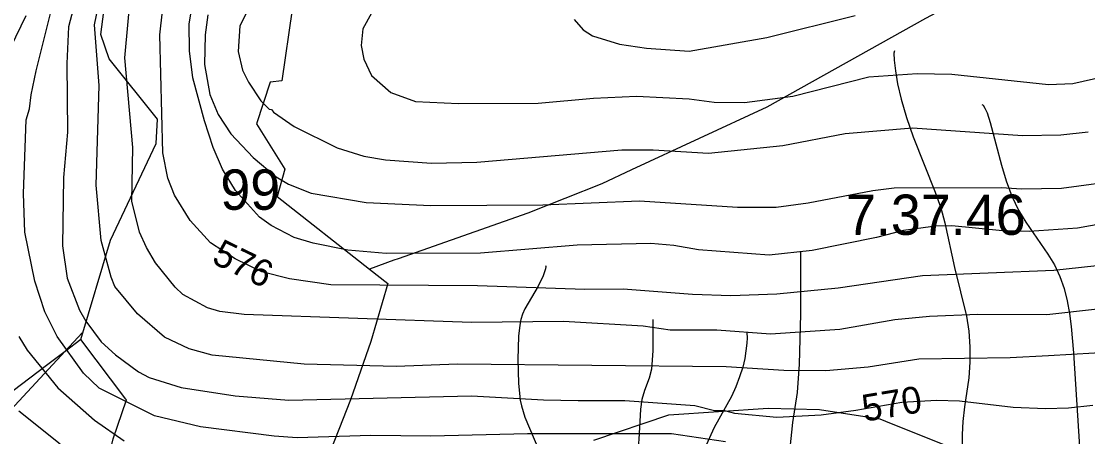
# Model space of a CAD drawing. Extents: x -709584 to -702006, y -1161789 to -1157496.
# Drawn here: x -707197.2 to -706800.1, y -1158463.2 to -1158308.6 of the extents above; entities that cross this region are included whole.
import ezdxf

# ---------------------------------------------------------------- set-up
doc = ezdxf.new("R2010")
doc.units = 0
for name, color, linetype in [('120_vrstevnice hlavní', 7, 'Continuous'), ('121_vrstevnice hlavní_popis', 7, 'Continuous'), ('122_vrstevnice základní', 7, 'Continuous'), ('408_BPEJ_linie', 7, 'Continuous'), ('409_BPEJ_popis', 7, 'Continuous'), ('411_akumulovaný odtok', 7, 'Continuous')]:
    doc.layers.add(name, color=color, linetype=linetype)

msp = doc.modelspace()

# ---------------------------------------------------------------- linework, layer by layer
at = {"layer": '120_vrstevnice hlavní'}
for points in [[(-707177.9, -1158304.1), (-707179.63, -1158310.68)], [(-707127.71, -1158306.12), (-707128.71, -1158313.55), (-707129, -1158324.7), (-707127, -1158335.84), (-707123.85, -1158343.27), (-707119.14, -1158350.41), (-707110.85, -1158359.27), (-707102.28, -1158366.41), (-707097.71, -1158369.13), (-707089.28, -1158372.56), (-707068.71, -1158375.99), (-707044.71, -1158377.13), (-707002.99, -1158376.84), (-706966.99, -1158375.41), (-706930.42, -1158377.7), (-706916.13, -1158377.7), (-706904.13, -1158376.13), (-706880.13, -1158371.56), (-706872.13, -1158370.56), (-706832.13, -1158370.41), (-706824.7, -1158370.98), (-706809.84, -1158370.7), (-706785.84, -1158367.41)], [(-707179.63, -1158310.68), (-707180.17, -1158324.22), (-707180, -1158349.84), (-707181.43, -1158366.7), (-707181.86, -1158392.13), (-707180.14, -1158404.13), (-707175.43, -1158416.13), (-707173.14, -1158420.13), (-707167.43, -1158427.84), (-707162.14, -1158432.7), (-707153.57, -1158438.99), (-707149.57, -1158441.13), (-707137.57, -1158444.84), (-707117.57, -1158447.99), (-707097.57, -1158449.56), (-707029.56, -1158447.99), (-707002.71, -1158449.42), (-706989.85, -1158449.7), (-706972.42, -1158449.7), (-706946.42, -1158451.56), (-706938.99, -1158453.42), (-706935.27, -1158453.42), (-706931.56, -1158454.42), (-706915.84, -1158455.85), (-706899.27, -1158454.99), (-706886.41, -1158453.27), (-706869.27, -1158450.27), (-706856.41, -1158449.56), (-706847.84, -1158449.84), (-706827.84, -1158452.13), (-706815.84, -1158452.7), (-706807.27, -1158452.42), (-706798.12, -1158451.42)]]:
    msp.add_lwpolyline(points, dxfattribs=at)
at = {"layer": '122_vrstevnice základní'}
for points in [[(-707194.14, -1158341.13), (-707193.54, -1158335.89), (-707191.58, -1158326.95), (-707186.28, -1158305.72), (-707183.48, -1158297.62), (-707179.57, -1158288.68), (-707172.29, -1158274.98), (-707165.57, -1158257.84), (-707139.57, -1158216.69), (-707132.14, -1158202.41), (-707128.71, -1158194.41), (-707111.71, -1158144.4), (-707107, -1158124.4), (-707102.85, -1158094.4), (-707101.71, -1158080.69), (-707101.85, -1158059.26), (-707103.28, -1158048.97), (-707105, -1158023.82), (-707101.71, -1157974.11)], [(-706792.12, -1158399.13), (-706812.7, -1158401.27), (-706861.56, -1158403.27), (-706892.99, -1158407.84), (-706915.84, -1158410.13), (-706932.99, -1158410.7), (-706947.27, -1158410.27), (-706972.99, -1158408.27), (-706987.28, -1158408.42), (-707027.28, -1158406.99), (-707081.85, -1158406.7), (-707097.28, -1158404.42), (-707107.57, -1158401.84), (-707117.57, -1158396.99), (-707126.71, -1158390.99), (-707134.28, -1158382.7), (-707140.14, -1158373.27), (-707142.57, -1158366.98), (-707144.43, -1158357.55), (-707145.57, -1158313.55), (-707143.43, -1158294.7)], [(-706788.98, -1158431.56), (-706814.7, -1158433.13), (-706828.98, -1158433.84), (-706862.98, -1158434.27), (-706881.84, -1158437.27), (-706897.56, -1158438.7), (-706913.27, -1158438.56), (-706934.7, -1158437.13), (-707034.71, -1158436.13), (-707057.57, -1158436.99), (-707091.85, -1158436.13), (-707126.14, -1158432.84), (-707134.71, -1158430.42), (-707143.85, -1158426.13), (-707153.86, -1158417.42), (-707162.28, -1158407.27), (-707163.71, -1158403.84), (-707167.43, -1158390.13), (-707169.29, -1158369.56), (-707168.14, -1158332.41), (-707169.86, -1158309.84), (-707167.28, -1158297.27)], [(-706776.41, -1158413.42), (-706815.27, -1158417.84), (-706840.98, -1158417.7), (-706858.98, -1158418.42), (-706871.84, -1158419.7), (-706892.42, -1158423.27), (-706918.13, -1158424.99), (-706938.13, -1158423.56), (-706955.56, -1158423.56), (-706965.56, -1158421.99), (-706995.28, -1158420.27), (-707029.56, -1158420.7), (-707114.14, -1158417.7), (-707123.28, -1158416.56), (-707127.85, -1158415.27), (-707137, -1158410.27), (-707139.85, -1158407.56), (-707147.14, -1158398.42), (-707150.57, -1158392.7), (-707153.14, -1158386.99), (-707156, -1158375.56), (-707155.57, -1158355.55), (-707158.57, -1158322.12), (-707156.28, -1158296.41)], [(-706767.84, -1158379.13), (-706803.84, -1158385.56), (-706821.84, -1158386.84), (-706831.84, -1158386.56), (-706850.7, -1158384.7), (-706856.7, -1158384.84), (-706868.7, -1158386.41), (-706878.7, -1158388.99), (-706902.7, -1158393.84), (-706918.7, -1158395.56), (-706945.05, -1158393.59), (-706954.13, -1158391.99), (-706962.7, -1158391.27), (-706990.13, -1158391.84), (-707026.14, -1158394.84), (-707061.28, -1158394.99), (-707075.57, -1158393.7), (-707088.42, -1158391.13), (-707095.57, -1158388.99), (-707104.14, -1158384.56), (-707108.43, -1158381.41), (-707117.43, -1158371.56), (-707122.28, -1158363.56), (-707125.71, -1158355.55), (-707129, -1158345.55), (-707133.28, -1158329.55), (-707134.57, -1158319.55), (-707134.71, -1158309.55), (-707133.28, -1158301.55)], [(-707111.18, -1158301.33), (-707115.83, -1158310.31), (-707116.43, -1158319.84), (-707114.85, -1158326.7), (-707112.57, -1158331.27), (-707108, -1158338.13), (-707104.85, -1158341.27), (-707104, -1158341.41), (-707103.28, -1158342.41), (-707095.57, -1158347.7), (-707079.57, -1158355.7), (-707069.57, -1158358.7), (-707061.57, -1158360.13), (-707044.42, -1158361.41), (-707027.56, -1158360.98), (-706973.56, -1158356.41), (-706961.85, -1158356.41), (-706941.27, -1158357.7), (-706913.56, -1158354.84), (-706890.41, -1158350.27), (-706865.27, -1158348.27), (-706824.41, -1158351.13), (-706810.12, -1158350.84), (-706799.84, -1158349.7)], [(-707066.71, -1158305.55), (-707069.99, -1158311.41), (-707070.57, -1158317.55), (-707069.57, -1158322.7), (-707066.71, -1158328.7), (-707059.57, -1158335.12), (-707050.42, -1158338.41), (-707034.42, -1158339.13), (-707004.71, -1158338.98), (-706984.13, -1158337.12), (-706968.13, -1158336.41), (-706948.42, -1158337.41), (-706939.13, -1158338.7), (-706927.84, -1158338.84), (-706909.84, -1158336.41), (-706881.56, -1158329.27), (-706863.56, -1158327.98), (-706850.7, -1158328.27), (-706814.7, -1158332.12), (-706805.55, -1158331.7), (-706794.12, -1158329.12)], [(-706991.28, -1158307.84), (-706987.99, -1158311.7), (-706984.42, -1158313.98), (-706974.42, -1158317.12), (-706964.42, -1158318.55), (-706948.42, -1158319.7), (-706919.56, -1158314.55), (-706886.7, -1158306.41)], [(-706934.99, -1158465.13), (-706954.99, -1158462.13), (-707008.71, -1158462.13), (-707044.71, -1158462.99), (-707066.99, -1158462.7), (-707094.42, -1158463.56), (-707103, -1158462.99), (-707130.43, -1158459.56), (-707147.57, -1158455.42), (-707168.14, -1158445.13), (-707174, -1158439.56), (-707183.86, -1158425.84), (-707188.43, -1158416.7), (-707192.14, -1158405.27), (-707195.86, -1158386.99), (-707196.29, -1158372.7), (-707195.29, -1158345.27), (-707194.14, -1158341.13)], [(-707198.14, -1158425.84), (-707195, -1158430.99), (-707183.57, -1158444.99), (-707169.86, -1158456.99), (-707158.86, -1158464.7)], [(-707182.71, -1158465.99), (-707198.14, -1158453.7)]]:
    msp.add_lwpolyline(points, dxfattribs=at)
at = {"layer": '408_BPEJ_linie'}
for points in [[(-706793.76, -1158269.39), (-706803, -1158275.5), (-706803.56, -1158275.81), (-706806.98, -1158277.72), (-706856.56, -1158305.39), (-706860.44, -1158307.55), (-706919.5, -1158340.5), (-706969.95, -1158363.88), (-706981, -1158369), (-707008.5, -1158380), (-707056.87, -1158396.93), (-707058.5, -1158397.5), (-707067.47, -1158400.85)], [(-707175, -1158427), (-707164, -1158390), (-707147, -1158354), (-707146.5, -1158345), (-707164.5, -1158322.5), (-707167.5, -1158313.5), (-707163.5, -1158282)], [(-707096.33, -1158304.15), (-707100.16, -1158330.72), (-707104.47, -1158331.16), (-707109.64, -1158346.76), (-707098.99, -1158363.54), (-707101.86, -1158373.8), (-707067.47, -1158400.85)], [(-707195.5, -1158306.5), (-707220.5, -1158358), (-707227.18, -1158396.03), (-707231.16, -1158418.72), (-707237, -1158452), (-707238.44, -1158459.36), (-707239.65, -1158465.56), (-707241.5, -1158475), (-707246, -1158489)], [(-707067.47, -1158400.85), (-707060.67, -1158406.2), (-707066.96, -1158427.71), (-707074.56, -1158449.42), (-707086.27, -1158479.05), (-707087.94, -1158482.96), (-707126.5, -1158483.16), (-707129.69, -1158483.46), (-707138.5, -1158476.5), (-707144.99, -1158484.88), (-707152.88, -1158485.61), (-707163.52, -1158482.93), (-707167, -1158480.5), (-707163, -1158464), (-707158, -1158449.5), (-707158.24, -1158449.18), (-707175, -1158427)], [(-707175, -1158427), (-707180.85, -1158431.43), (-707187.82, -1158436.71), (-707222.5, -1158463), (-707230.79, -1158472.17), (-707234.48, -1158476.26), (-707246, -1158489)], [(-706984, -1158464.5), (-706956, -1158455), (-706919, -1158452.5), (-706900, -1158453), (-706879.82, -1158456.14), (-706877.5, -1158456.5), (-706875.4, -1158457.34), (-706829, -1158476)]]:
    msp.add_lwpolyline(points, dxfattribs=at)
at = {"layer": '411_akumulovaný odtok'}
for points in [[(-706871.99, -1158319.5), (-706872.2, -1158320.48), (-706872.11, -1158323.04), (-706871.69, -1158326.94), (-706870.88, -1158331.88), (-706869.59, -1158337.6), (-706867.57, -1158344.41), (-706865.05, -1158351.54), (-706856.86, -1158372.2), (-706854.8, -1158378.02), (-706853.25, -1158383.53), (-706849.67, -1158400.24), (-706845.16, -1158418.27), (-706844.31, -1158423.95), (-706843.92, -1158429.71), (-706843.95, -1158435.49), (-706844.37, -1158441.24), (-706845.93, -1158452.11), (-706846.55, -1158457.53), (-706846.76, -1158462.31), (-706846.57, -1158476.7)], [(-706839.49, -1158339.5), (-706839.03, -1158339.78), (-706838.36, -1158340.85), (-706837.55, -1158342.62), (-706836.34, -1158346.22), (-706832.23, -1158362.05), (-706830.47, -1158367.97), (-706828.35, -1158373.66), (-706825.8, -1158378.88), (-706823.06, -1158383.38), (-706814.87, -1158395.19), (-706812.44, -1158399.27), (-706810.39, -1158403.52), (-706808.85, -1158407.96), (-706807.71, -1158412.57), (-706806.86, -1158417.31), (-706806.21, -1158422.15), (-706805.3, -1158432), (-706803.11, -1158466.89)], [(-706906.99, -1158394.5), (-706906.97, -1158417.55), (-706907.47, -1158436.23), (-706908.28, -1158446.74), (-706909.98, -1158457.88), (-706911.04, -1158467.39)], [(-707001.99, -1158399.5), (-707001.88, -1158399.85), (-707001.97, -1158400.65), (-707002.79, -1158403.32), (-707004.72, -1158407.15), (-707009.68, -1158415.63), (-707010.57, -1158417.6), (-707011.18, -1158419.58), (-707011.58, -1158421.61), (-707012.03, -1158425.82), (-707012.26, -1158434.49), (-707012.05, -1158443.21), (-707011.38, -1158449.64), (-707010.94, -1158451.73), (-707009.61, -1158455.91), (-707004.39, -1158468.14)], [(-706961.99, -1158419.5), (-706962, -1158431.25), (-706962.53, -1158438.01), (-706963.33, -1158441.45), (-706965.14, -1158446), (-706966.1, -1158449.29), (-706966.61, -1158452.92), (-706967.17, -1158464.22), (-706967.55, -1158467.91), (-706968.35, -1158471.44), (-706971.53, -1158479.19), (-706972.87, -1158484.43), (-706974.42, -1158493.57), (-706976.99, -1158512)], [(-707174.49, -1158424.5), (-707221.65, -1158475.24), (-707231.23, -1158485.07), (-707237.78, -1158491.27), (-707241.15, -1158494.17), (-707244.62, -1158496.88), (-707248.21, -1158499.34), (-707260.11, -1158506.24), (-707267.45, -1158511.21), (-707274.65, -1158516.59), (-707281.72, -1158522.28), (-707288.75, -1158528.33), (-707299.13, -1158537.68), (-707346.99, -1158582)], [(-706926.99, -1158424.5), (-706926.89, -1158426.35), (-706926.99, -1158428.39), (-706927.75, -1158434.01), (-706928.51, -1158437.29), (-706929.67, -1158440.95), (-706931.12, -1158444.62), (-706932.77, -1158448.18), (-706939.13, -1158459.8), (-706940.45, -1158462.46), (-706944.24, -1158471.08)]]:
    msp.add_lwpolyline(points, dxfattribs=at)

# ---------------------------------------------------------------- texts
at = {"layer": '121_vrstevnice hlavní_popis'}
for s, rotation, p in [('576', 334.0603, (-707126.7, -1158398.31)), ('570', 9.5355, (-706883.23, -1158457.64))]:
    msp.add_text(s, height=10, rotation=rotation, dxfattribs=at).set_placement(p)
at = {"layer": '409_BPEJ_popis'}
for s, p in [('99', (-707123.06, -1158378.71)), ('7.37.46', (-706890.1, -1158388.06))]:
    msp.add_text(s, height=15, dxfattribs=at).set_placement(p)

doc.saveas('drawing.dxf')
